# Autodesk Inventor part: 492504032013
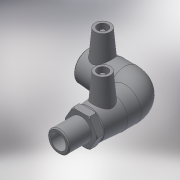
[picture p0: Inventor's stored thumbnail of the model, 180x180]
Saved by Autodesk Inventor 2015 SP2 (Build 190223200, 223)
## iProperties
Created: 2017-06
Part Number: 492504032013
Material: Generic
Description: PLASSON 90° ELBOW MALE TRANSITION 32-1.1/4"
Document SubType Name: Modeling
Designer: KIM
Mass: 132.856 g
Surface Area: 411.515 cm^2
Volume: 132.856 cm^3
Density: 1 g/cm^3
Appearance: Default
Author: KIM
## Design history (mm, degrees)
derived "492504.ipt"
feature "Solid1::492504.ipt"
tag "TaggingFeature1"
body "Solid1"
other parameters: "d2" = 44, "d4" = 27.66667, "d5" = 39.6, "d8" = 168 deg, "d10" = 16, "d11" = 5.33333, "d29" = 43, "d30" = 15, "d31" = 45.65, "d34" = 5 deg, "d41" = 4, "d42" = 14, "d43" = 0, "d48" = 61, "d49" = 32, "d50" = 27.2, "d51" = 16, "d54" = 90 deg, "d57" = 32, "d59" = 0, "d61" = 90 deg, "d86" = 3, "d87" = 0, "d93" = 0.1, "d94" = 9, "d95" = 41.91, "d96" = 29.337, "d97" = 23, "d98" = 36, "d99" = 52.8, "d100" = 32.4, "d102" = 1.6, "d106" = 0, "d_" = 32, "L_" = 119, "D_" = 23, "A_" = 43, "d_2" = 12, "L_2" = 36, "D_1" = 44, "R_" = 41.91
